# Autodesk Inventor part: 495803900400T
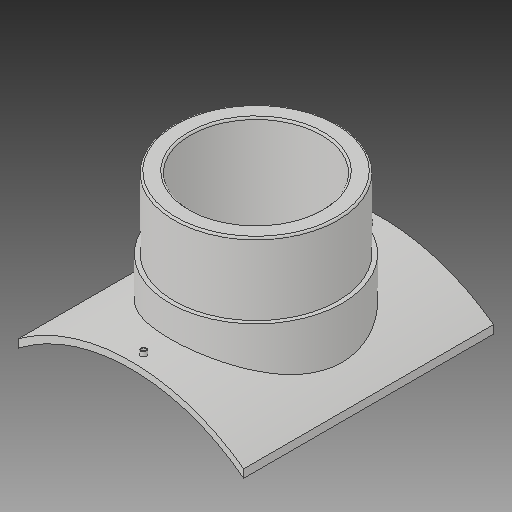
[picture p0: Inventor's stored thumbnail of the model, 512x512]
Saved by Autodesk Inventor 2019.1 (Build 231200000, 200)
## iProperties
Created: 2017-10
Part Number: 495803900400T
Material: Generic
Description: PLASSON BRANCH SADDLE  900x400
Document SubType Name: Modeling
Designer: KIM
Mass: 2754.05 g
Surface Area: 3037.44 cm^2
Volume: 2754.05 cm^3
Density: 1 g/cm^3
Appearance: Default
Author: KIM
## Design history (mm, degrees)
derived "495803.ipt"
feature "Solid1::495803.ipt"
tag "TaggingFeature1"
body "Solid1"
other parameters: "d1" = 16, "d4" = 0, "d12" = 475.6, "d13" = 14, "d14" = 274.5, "d16" = 5 deg, "d18" = 4, "d19" = 14, "d20" = 0, "d21" = 3, "d22" = 0, "d23" = 716, "d25" = 16, "d28" = 0, "d29" = 9.6, "d31" = 0, "d32" = 125, "d33" = 0, "d34" = 9, "d37" = 175, "d38" = 0, "d39" = 4.5, "x_" = 16, "D_" = 16
